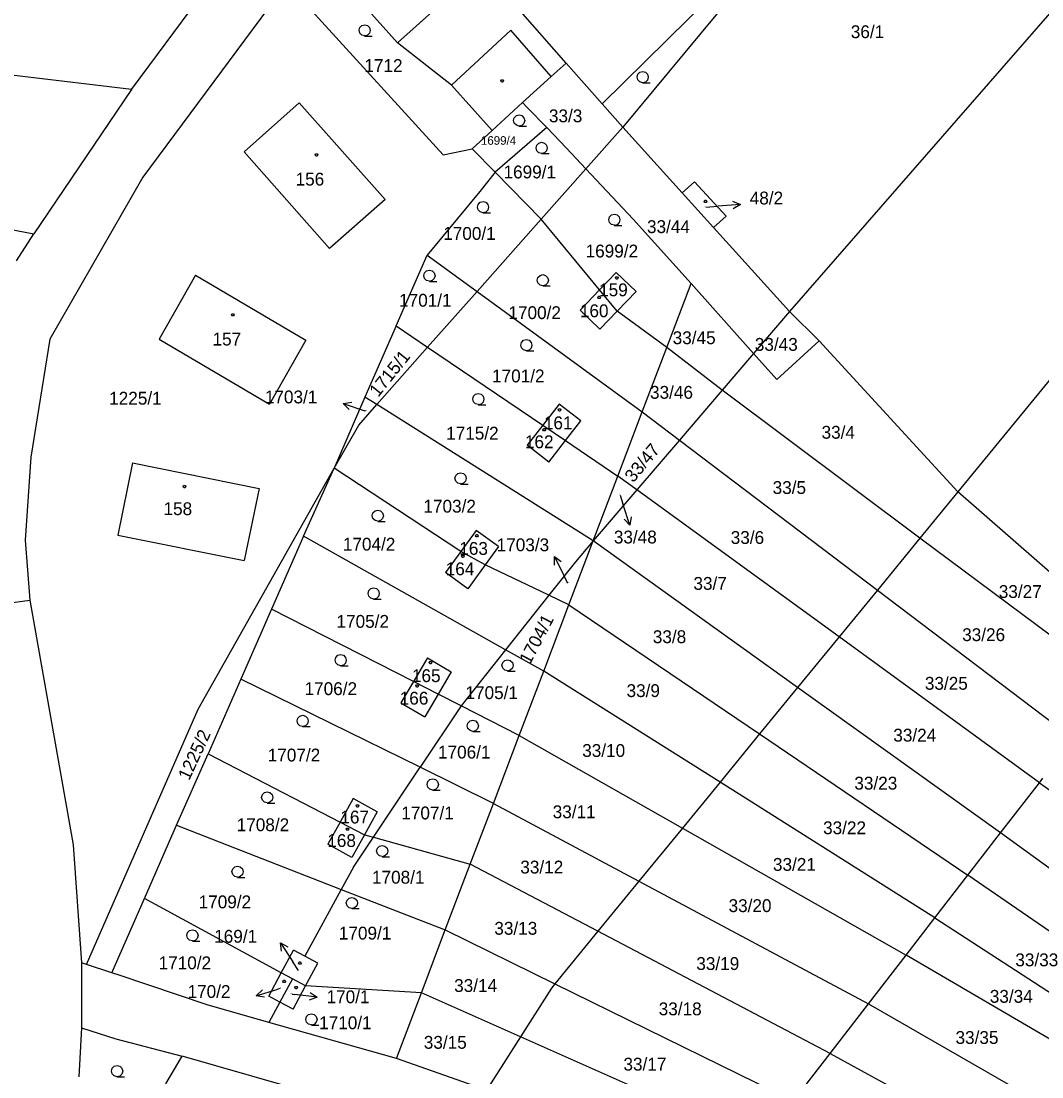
# Model space of a CAD drawing. Extents: x -802857 to -799647, y -1020285 to -1015884.
# Drawn here: x -801708.7 to -801573.5, y -1017921.9 to -1017782.1 of the extents above; entities that cross this region are included whole.
import ezdxf

# ---------------------------------------------------------------- set-up
doc = ezdxf.new("R2010")
doc.units = 0
for name, color, linetype in [('Default', 7, 'Continuous'), ('KN_HRANICE', 7, 'Continuous'), ('KN_KULTURY', 7, 'Continuous'), ('KN_PARCELY', 7, 'Continuous'), ('KN_SLUCKY', 7, 'Continuous')]:
    doc.layers.add(name, color=color, linetype=linetype)

# ---------------------------------------------------------------- blocks, each defined once
blk = doc.blocks.new('304')
at = {"layer": 'Default'}
blk.add_lwpolyline([(0, 0), (-0.38, 0.1), (-0.65, 0.37), (-0.75, 0.74), (-0.65, 1.11), (-0.38, 1.38), (-0.01, 1.48), (0.36, 1.38), (0.63, 1.11), (0.73, 0.73), (0.63, 0.35), (0.36, 0.08), (-0.02, -0.02), (0.98, -0.02)], dxfattribs=at)
blk = doc.blocks.new('10292')
at = {"layer": 'Default'}
blk.add_line((0, 3), (0, 0), dxfattribs=at)
blk.add_lwpolyline([(-0.5, 2), (0, 3), (0.5, 2)], dxfattribs=at)
blk = doc.blocks.new('402')
at = {"layer": 'Default'}
blk.add_lwpolyline([(0.09, 0.15), (0.18, 0), (0.09, -0.15), (-0.09, -0.15), (-0.18, 0), (-0.09, 0.15), (0.09, 0.15)], dxfattribs=at)

msp = doc.modelspace()

# ---------------------------------------------------------------- linework, layer by layer
at = {"layer": 'KN_HRANICE'}
for p, q in [((-801587.49, -1017746.18), (-801629.02, -1017796.14)), ((-801636.53, -1017787.69), (-801656.2, -1017765.17)), ((-801665.9, -1017766.77), (-801692.56, -1017802.78)), ((-801560.55, -1017767.41), (-801606.93, -1017820.56)), ((-801606.88, -1017768.59), (-801631.76, -1017793.06)), ((-801694.1, -1017791.18), (-801681, -1017773.54)), ((-801526.7, -1017773.73), (-801584.65, -1017844.45)), ((-801658.84, -1017785), (-801667.4, -1017775.47)), ((-801670.22, -1017780.7), (-801652.82, -1017799.83)), ((-801651.72, -1017790.61), (-801658.84, -1017785)), ((-801636.53, -1017787.69), (-801638.49, -1017789.43)), ((-801631.76, -1017793.06), (-801636.53, -1017787.69)), ((-801694.1, -1017791.18), (-801711.96, -1017789.03)), ((-801638.49, -1017789.43), (-801642.29, -1017792.91)), ((-801694.1, -1017791.18), (-801707.01, -1017810.3)), ((-801651.72, -1017790.61), (-801646.32, -1017796.61)), ((-801679.14, -1017799.41), (-801671.86, -1017792.92)), ((-801671.86, -1017792.92), (-801660.48, -1017805.72)), ((-801642.29, -1017792.91), (-801646.32, -1017796.61)), ((-801641.68, -1017793.54), (-801642.29, -1017792.91)), ((-801641.68, -1017793.54), (-801639.09, -1017796.22)), ((-801629.02, -1017796.14), (-801631.76, -1017793.06)), ((-801646.32, -1017796.61), (-801648.95, -1017799.02)), ((-801639.09, -1017796.22), (-801645.9, -1017802.13)), ((-801639.09, -1017796.22), (-801636.48, -1017798.92)), ((-801633.91, -1017801.66), (-801629.02, -1017796.14)), ((-801629.02, -1017796.14), (-801621.14, -1017804.85)), ((-801667.86, -1017812.23), (-801679.14, -1017799.41)), ((-801652.82, -1017799.83), (-801648.95, -1017799.02)), ((-801645.9, -1017802.13), (-801648.95, -1017799.02)), ((-801636.48, -1017798.92), (-801633.91, -1017801.66)), ((-801754.22, -1017801.07), (-801707.01, -1017810.3)), ((-801645.9, -1017802.13), (-801647.97, -1017804.68)), ((-801645.9, -1017802.13), (-801639.83, -1017808.34)), ((-801639.83, -1017808.34), (-801633.91, -1017801.66)), ((-801633.91, -1017801.66), (-801627.63, -1017808.36)), ((-801692.56, -1017802.78), (-801704.91, -1017824.25)), ((-801621.14, -1017804.85), (-801619.52, -1017803.38)), ((-801619.52, -1017803.38), (-801615.33, -1017807.93)), ((-801647.97, -1017804.68), (-801654.93, -1017813.11)), ((-801621.14, -1017804.85), (-801616.99, -1017809.44)), ((-801660.48, -1017805.72), (-801667.86, -1017812.23)), ((-801616.99, -1017809.44), (-801615.33, -1017807.93)), ((-801648.32, -1017817.92), (-801639.83, -1017808.34)), ((-801632.1, -1017817.7), (-801639.83, -1017808.34)), ((-801627.63, -1017808.36), (-801619.98, -1017816.88)), ((-801616.99, -1017809.44), (-801606.93, -1017820.56)), ((-801709.32, -1017813.86), (-801707.01, -1017810.3)), ((-801659.05, -1017822.48), (-801654.93, -1017813.11)), ((-801654.93, -1017813.11), (-801648.32, -1017817.92)), ((-801685.6, -1017815.77), (-801690.43, -1017824.24)), ((-801685.6, -1017815.77), (-801670.98, -1017824.37)), ((-801632.1, -1017817.7), (-801629.89, -1017815.39)), ((-801627.26, -1017817.92), (-801629.89, -1017815.39)), ((-801654.87, -1017825.31), (-801648.32, -1017817.92)), ((-801648.32, -1017817.92), (-801626.43, -1017833.85)), ((-801634.67, -1017820.37), (-801632.1, -1017817.7)), ((-801629.76, -1017820.53), (-801632.1, -1017817.7)), ((-801627.26, -1017817.92), (-801629.76, -1017820.53)), ((-801623.2, -1017825.34), (-801619.98, -1017816.88)), ((-801619.98, -1017816.88), (-801611.69, -1017826.12)), ((-801632.04, -1017822.9), (-801634.67, -1017820.37)), ((-801629.76, -1017820.53), (-801632.04, -1017822.9)), ((-801623.2, -1017825.34), (-801629.76, -1017820.53)), ((-801606.93, -1017820.56), (-801611.69, -1017826.12)), ((-801603.03, -1017824.46), (-801606.93, -1017820.56)), ((-801659.05, -1017822.48), (-801663.18, -1017831.89)), ((-801659.05, -1017822.48), (-801654.87, -1017825.31)), ((-801704.91, -1017824.25), (-801707.43, -1017839.85)), ((-801690.43, -1017824.24), (-801675.81, -1017832.84)), ((-801670.98, -1017824.37), (-801675.81, -1017832.84)), ((-801608.61, -1017829.56), (-801603.03, -1017824.46)), ((-801603.03, -1017824.46), (-801584.65, -1017844.45)), ((-801661.59, -1017832.89), (-801654.87, -1017825.31)), ((-801654.87, -1017825.31), (-801639.62, -1017835.62)), ((-801626.43, -1017833.85), (-801623.2, -1017825.34)), ((-801615.84, -1017830.97), (-801623.2, -1017825.34)), ((-801611.69, -1017826.12), (-801615.84, -1017830.97)), ((-801611.69, -1017826.12), (-801608.61, -1017829.56)), ((-801663.18, -1017831.89), (-801667.22, -1017841.33)), ((-801661.59, -1017832.89), (-801663.18, -1017831.89)), ((-801615.84, -1017830.97), (-801621.5, -1017837.59)), ((-801589.67, -1017850.59), (-801615.84, -1017830.97)), ((-801663.99, -1017835.6), (-801661.59, -1017832.89)), ((-801632.93, -1017850.94), (-801661.59, -1017832.89)), ((-801637.45, -1017832.82), (-801639.62, -1017835.62)), ((-801634.57, -1017835.06), (-801637.45, -1017832.82)), ((-801629.66, -1017842.35), (-801626.43, -1017833.85)), ((-801626.43, -1017833.85), (-801621.5, -1017837.59)), ((-801667.22, -1017841.33), (-801663.99, -1017835.6)), ((-801639.62, -1017835.62), (-801641.68, -1017838.27)), ((-801639.62, -1017835.62), (-801636.59, -1017837.67)), ((-801636.59, -1017837.67), (-801634.57, -1017835.06)), ((-801621.5, -1017837.59), (-801627.15, -1017844.18)), ((-801621.5, -1017837.59), (-801595.3, -1017857.46)), ((-801638.8, -1017840.51), (-801641.68, -1017838.27)), ((-801638.8, -1017840.51), (-801636.59, -1017837.67)), ((-801636.59, -1017837.67), (-801629.66, -1017842.35)), ((-801707.43, -1017839.85), (-801708.15, -1017850.85)), ((-801693.95, -1017840.61), (-801695.91, -1017850.17)), ((-801693.95, -1017840.61), (-801677.18, -1017843.99)), ((-801685.23, -1017873.24), (-801667.22, -1017841.33)), ((-801671.28, -1017850.32), (-801667.22, -1017841.33)), ((-801650.45, -1017852.35), (-801667.22, -1017841.33)), ((-801632.93, -1017850.94), (-801629.66, -1017842.35)), ((-801627.15, -1017844.18), (-801629.66, -1017842.35)), ((-801677.18, -1017843.99), (-801679.14, -1017853.55)), ((-801627.15, -1017844.18), (-801632.93, -1017850.94)), ((-801600.38, -1017863.66), (-801627.15, -1017844.18)), ((-801584.65, -1017844.45), (-801589.67, -1017850.59)), ((-801566.54, -1017860.25), (-801584.65, -1017844.45)), ((-801695.91, -1017850.17), (-801679.14, -1017853.55)), ((-801648.43, -1017849.55), (-801650.45, -1017852.35)), ((-801645.48, -1017851.7), (-801648.43, -1017849.55)), ((-801708.15, -1017850.85), (-801707.54, -1017858.79)), ((-801671.28, -1017850.32), (-801675.52, -1017859.98)), ((-801644.53, -1017865.36), (-801671.28, -1017850.32)), ((-801636.14, -1017859.39), (-801632.93, -1017850.94)), ((-801632.93, -1017850.94), (-801635.29, -1017853.7)), ((-801605.86, -1017870.35), (-801632.93, -1017850.94)), ((-801589.67, -1017850.59), (-801595.3, -1017857.46)), ((-801563.11, -1017870.36), (-801589.67, -1017850.59)), ((-801650.45, -1017852.35), (-801652.49, -1017855.13)), ((-801647.25, -1017854.13), (-801650.45, -1017852.35)), ((-801645.48, -1017851.7), (-801647.25, -1017854.13)), ((-801647.25, -1017854.13), (-801649.54, -1017857.28)), ((-801638.8, -1017858.13), (-801647.25, -1017854.13)), ((-801635.29, -1017853.7), (-801638.8, -1017858.13)), ((-801649.54, -1017857.28), (-801652.49, -1017855.13)), ((-801638.8, -1017858.13), (-801644.53, -1017865.36)), ((-801636.14, -1017859.39), (-801638.8, -1017858.13)), ((-801595.3, -1017857.46), (-801600.38, -1017863.66)), ((-801595.3, -1017857.46), (-801569.08, -1017877.35)), ((-801717.29, -1017860.13), (-801707.54, -1017858.79)), ((-801707.54, -1017858.79), (-801701.82, -1017891.2)), ((-801675.52, -1017859.98), (-801679.59, -1017869.24)), ((-801656.73, -1017869.56), (-801675.52, -1017859.98)), ((-801639.49, -1017868.19), (-801636.14, -1017859.39)), ((-801636.14, -1017859.39), (-801610.9, -1017876.51)), ((-801600.38, -1017863.66), (-801605.86, -1017870.35)), ((-801573.84, -1017882.97), (-801600.38, -1017863.66)), ((-801644.53, -1017865.36), (-801650.41, -1017872.78)), ((-801639.49, -1017868.19), (-801644.53, -1017865.36)), ((-801654.89, -1017866.43), (-801656.73, -1017869.56)), ((-801654.89, -1017866.43), (-801651.74, -1017868.29)), ((-801651.74, -1017868.29), (-801653.47, -1017871.22)), ((-801642.73, -1017876.71), (-801639.49, -1017868.19)), ((-801616.14, -1017882.9), (-801639.49, -1017868.19)), ((-801679.59, -1017869.24), (-801683.94, -1017879.14)), ((-801655.86, -1017880.92), (-801679.59, -1017869.24)), ((-801656.73, -1017869.56), (-801658.39, -1017872.37)), ((-801653.47, -1017871.22), (-801656.73, -1017869.56)), ((-801605.86, -1017870.35), (-801610.9, -1017876.51)), ((-801578.98, -1017889.62), (-801605.86, -1017870.35)), ((-801658.39, -1017872.37), (-801655.25, -1017874.23)), ((-801653.47, -1017871.22), (-801655.25, -1017874.23)), ((-801650.41, -1017872.78), (-801653.47, -1017871.22)), ((-801700.05, -1017907.03), (-801685.23, -1017873.24)), ((-801650.41, -1017872.78), (-801655.86, -1017880.92)), ((-801642.73, -1017876.71), (-801650.41, -1017872.78)), ((-801646.15, -1017885.7), (-801642.73, -1017876.71)), ((-801642.73, -1017876.71), (-801621.12, -1017888.98)), ((-801610.9, -1017876.51), (-801616.14, -1017882.9)), ((-801610.9, -1017876.51), (-801583.31, -1017895.22)), ((-801688.1, -1017888.6), (-801683.94, -1017879.14)), ((-801683.94, -1017879.14), (-801666.46, -1017888.17)), ((-801662.05, -1017890.18), (-801655.86, -1017880.92)), ((-801646.15, -1017885.7), (-801655.86, -1017880.92)), ((-801573.84, -1017882.97), (-801573.38, -1017882.38)), ((-801616.14, -1017882.9), (-801621.12, -1017888.98)), ((-801587.67, -1017900.85), (-801616.14, -1017882.9)), ((-801578.98, -1017889.62), (-801573.84, -1017882.97)), ((-801573.84, -1017882.97), (-801548.75, -1017900.91)), ((-801664.73, -1017885.06), (-801666.46, -1017888.17)), ((-801661.54, -1017886.83), (-801664.73, -1017885.06)), ((-801649.21, -1017893.75), (-801646.15, -1017885.7)), ((-801646.15, -1017885.7), (-801626.87, -1017896)), ((-801661.54, -1017886.83), (-801663.22, -1017889.85)), ((-801692.35, -1017898.29), (-801688.1, -1017888.6)), ((-801688.1, -1017888.6), (-801666.31, -1017897.09)), ((-801666.46, -1017888.17), (-801668.08, -1017891.09)), ((-801666.46, -1017888.17), (-801663.22, -1017889.85)), ((-801621.12, -1017888.98), (-801626.87, -1017896)), ((-801621.12, -1017888.98), (-801591.49, -1017905.8)), ((-801663.22, -1017889.85), (-801664.89, -1017892.87)), ((-801664.7, -1017894.14), (-801662.05, -1017890.18)), ((-801663.22, -1017889.85), (-801662.05, -1017890.18)), ((-801662.05, -1017890.18), (-801649.21, -1017893.75)), ((-801583.31, -1017895.22), (-801578.98, -1017889.62)), ((-801554.19, -1017907.62), (-801578.98, -1017889.62)), ((-801701.82, -1017891.2), (-801700.72, -1017906.81)), ((-801664.89, -1017892.87), (-801668.08, -1017891.09)), ((-801664.7, -1017894.14), (-801666.31, -1017897.09)), ((-801652.52, -1017902.46), (-801649.21, -1017893.75)), ((-801632.31, -1017902.64), (-801649.21, -1017893.75)), ((-801626.87, -1017896), (-801632.31, -1017902.64)), ((-801626.87, -1017896), (-801596.46, -1017912.23)), ((-801587.67, -1017900.85), (-801583.31, -1017895.22)), ((-801558.14, -1017912.49), (-801583.31, -1017895.22)), ((-801666.31, -1017897.09), (-801671.13, -1017905.94)), ((-801666.31, -1017897.09), (-801652.52, -1017902.46)), ((-801696.68, -1017908.14), (-801692.35, -1017898.29)), ((-801674.24, -1017908.14), (-801692.35, -1017898.29)), ((-801591.49, -1017905.8), (-801587.67, -1017900.85)), ((-801587.67, -1017900.85), (-801562.14, -1017917.44)), ((-801655.69, -1017910.79), (-801652.52, -1017902.46)), ((-801652.52, -1017902.46), (-801638, -1017909.59)), ((-801632.31, -1017902.64), (-801638, -1017909.59)), ((-801601.56, -1017918.81), (-801632.31, -1017902.64)), ((-801674.24, -1017908.14), (-801672.63, -1017905.14)), ((-801671.13, -1017905.94), (-801672.63, -1017905.14)), ((-801669.41, -1017906.86), (-801671.13, -1017905.94)), ((-801596.46, -1017912.23), (-801591.49, -1017905.8)), ((-801565.18, -1017921.19), (-801591.49, -1017905.8)), ((-801700.72, -1017906.81), (-801700.71, -1017915.44)), ((-801700.05, -1017907.03), (-801700.72, -1017906.81)), ((-801696.68, -1017908.14), (-801700.05, -1017907.03)), ((-801671.02, -1017909.86), (-801669.41, -1017906.86)), ((-801695.73, -1017908.45), (-801696.68, -1017908.14)), ((-801684.06, -1017912.38), (-801695.73, -1017908.45)), ((-801675.89, -1017911.22), (-801674.24, -1017908.14)), ((-801672.76, -1017908.93), (-801674.43, -1017912)), ((-801672.76, -1017908.93), (-801674.24, -1017908.14)), ((-801671.02, -1017909.86), (-801672.76, -1017908.93)), ((-801672.67, -1017912.94), (-801671.02, -1017909.86)), ((-801655.69, -1017910.79), (-801671.02, -1017909.86)), ((-801638.47, -1017910.16), (-801642.56, -1017916.61)), ((-801638, -1017909.59), (-801638.47, -1017910.16)), ((-801638, -1017909.59), (-801606.41, -1017925.09)), ((-801674.43, -1017912), (-801675.89, -1017911.22)), ((-801659, -1017919.5), (-801655.69, -1017910.79)), ((-801642.56, -1017916.61), (-801655.69, -1017910.79)), ((-801675.91, -1017914.7), (-801684.06, -1017912.38)), ((-801674.43, -1017912), (-801675.91, -1017914.7)), ((-801672.67, -1017912.94), (-801674.43, -1017912)), ((-801601.56, -1017918.81), (-801596.46, -1017912.23)), ((-801596.46, -1017912.23), (-801570.17, -1017927.35)), ((-801700.71, -1017915.44), (-801701.04, -1017921.92)), ((-801700.71, -1017915.44), (-801696.14, -1017916.89)), ((-801659, -1017919.5), (-801675.91, -1017914.7)), ((-801696.14, -1017916.89), (-801687.37, -1017919.18)), ((-801642.56, -1017916.61), (-801647.06, -1017923.69)), ((-801610.75, -1017930.7), (-801642.56, -1017916.61)), ((-801689.53, -1017922.82), (-801687.37, -1017919.18)), ((-801669.21, -1017924.37), (-801687.37, -1017919.18)), ((-801647.06, -1017923.69), (-801659, -1017919.5)), ((-801606.41, -1017925.09), (-801601.56, -1017918.81)), ((-801601.56, -1017918.81), (-801575.03, -1017933.33))]:
    msp.add_line(p, q, dxfattribs=at)
at = {"layer": 'KN_PARCELY'}
for p, q in [((-801618.02, -1017806.73), (-801616.43, -1017806.61)), ((-801663.11, -1017833.73), (-801663.19, -1017833.7)), ((-801629.38, -1017844.9), (-801629.01, -1017846.02)), ((-801636.29, -1017856.55), (-801636.72, -1017855.7)), ((-801671.96, -1017907.81), (-801672.71, -1017906.66)), ((-801674.38, -1017910.21), (-801674.68, -1017910.3)), ((-801672.82, -1017910.97), (-801672.47, -1017911.01))]:
    msp.add_line(p, q, dxfattribs=at)
at = {"layer": 'KN_SLUCKY'}
for p, q in [((-801652.2, -1017779.01), (-801658.84, -1017785)), ((-801651.72, -1017790.61), (-801643.83, -1017783.33)), ((-801638.49, -1017789.43), (-801643.83, -1017783.33))]:
    msp.add_line(p, q, dxfattribs=at)

# ---------------------------------------------------------------- block references
at = {"layer": 'KN_KULTURY'}
for name, p in [('304', (-801663.19, -1017784.07)), ('402', (-801645, -1017790.03)), ('304', (-801626.37, -1017790.27)), ('304', (-801642.73, -1017796.01)), ('304', (-801639.75, -1017799.64)), ('402', (-801669.57, -1017799.83)), ('304', (-801647.51, -1017807.49)), ('402', (-801618.08, -1017805.98)), ('304', (-801630.12, -1017809.15)), ('304', (-801654.61, -1017816.56)), ('304', (-801639.6, -1017817.16)), ('402', (-801629.79, -1017816.13)), ('402', (-801632.15, -1017818.7)), ('402', (-801680.68, -1017821.01)), ('304', (-801641.77, -1017825.76)), ('304', (-801648.14, -1017832.9)), ('402', (-801637.41, -1017833.6)), ('402', (-801639.42, -1017836.22)), ('304', (-801650.49, -1017843.39)), ('402', (-801687.08, -1017843.76)), ('304', (-801661.45, -1017848.34)), ('402', (-801648.35, -1017850.26)), ('402', (-801650.21, -1017852.98)), ('304', (-801662, -1017858.64)), ('304', (-801666.37, -1017867.47)), ('402', (-801654.48, -1017867.06)), ('304', (-801644.27, -1017868.15)), ('402', (-801656.25, -1017870.15)), ('304', (-801671.4, -1017875.52)), ('304', (-801648.87, -1017876.17)), ('304', (-801654.17, -1017883.93)), ('304', (-801676.1, -1017885.64)), ('402', (-801664.16, -1017886.03)), ('402', (-801665.49, -1017889.11)), ('304', (-801660.87, -1017892.74)), ('304', (-801680.03, -1017895.48)), ('304', (-801664.89, -1017899.62)), ('304', (-801686, -1017903.92)), ('402', (-801671.78, -1017906.84)), ('402', (-801673.88, -1017909.28)), ('402', (-801672.27, -1017910.09)), ('304', (-801670.24, -1017915.04)), ('304', (-801695.98, -1017921.89))]:
    msp.add_blockref(name, p, dxfattribs=at)
at = {"layer": 'KN_PARCELY'}
for p, rotation in [((-801616.43, -1017806.61), -85.78239900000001), ((-801663.19, -1017833.7), 71.104062), ((-801629.01, -1017846.02), -161.58471600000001), ((-801636.72, -1017855.7), 26.642537), ((-801672.71, -1017906.66), 33.231552), ((-801674.68, -1017910.3), 106.856629), ((-801672.47, -1017911.01), -96.840485)]:
    msp.add_blockref('10292', p, dxfattribs=dict(at, rotation=rotation))

# ---------------------------------------------------------------- texts
for s, height, p in [('36/1', 1.7, (-801598.82, -1017784.37)), ('1712', 1.7, (-801663.24, -1017788.85)), ('33/3', 1.7, (-801638.8, -1017795.51)), ('1699/4', 1.14, (-801647.8, -1017798.49)), ('1699/1', 1.7, (-801644.81, -1017802.94)), ('156', 1.7, (-801672.35, -1017803.89)), ('48/2', 1.7, (-801612.2, -1017806.39)), ('48/2', 0.1, (-801618.22, -1017806.73)), ('1700/1', 1.7, (-801652.8, -1017811.08)), ('33/44', 1.7, (-801625.81, -1017810.18)), ('1699/2', 1.7, (-801633.94, -1017813.41)), ('159', 1.7, (-801632.15, -1017818.55)), ('1701/1', 1.7, (-801658.64, -1017819.93)), ('1700/2', 1.7, (-801644.16, -1017821.57)), ('160', 1.7, (-801634.7, -1017821.32)), ('157', 1.7, (-801683.35, -1017825.07)), ('33/45', 1.7, (-801622.41, -1017824.89)), ('33/43', 1.7, (-801611.53, -1017825.77)), ('1701/2', 1.7, (-801646.33, -1017829.95)), ('33/46', 1.7, (-801625.41, -1017832.12)), ('1225/1', 1.7, (-801697.04, -1017832.9)), ('1703/1', 1.7, (-801676.42, -1017832.73)), ('1703/1', 0.1, (-801663.39, -1017833.73)), ('161', 1.7, (-801639.47, -1017836.16)), ('1715/2', 1.7, (-801652.41, -1017837.53)), ('33/4', 1.7, (-801602.69, -1017837.41)), ('162', 1.7, (-801641.98, -1017838.67)), ('33/5', 1.7, (-801609.17, -1017844.73)), ('158', 1.7, (-801689.84, -1017847.53)), ('1703/2', 1.7, (-801655.42, -1017847.2)), ('33/48', 0.1, (-801629.62, -1017844.9)), ('33/48', 1.7, (-801630.2, -1017851.28)), ('33/6', 1.7, (-801614.72, -1017851.34)), ('1704/2', 1.7, (-801666.09, -1017852.23)), ('163', 1.7, (-801650.67, -1017852.79)), ('1703/3', 1.7, (-801645.72, -1017852.31)), ('164', 1.7, (-801652.47, -1017855.49)), ('33/7', 1.7, (-801619.66, -1017857.42)), ('1703/3', 0.1, (-801636.59, -1017856.55)), ('33/27', 1.7, (-801579.22, -1017858.5)), ('1705/2', 1.7, (-801666.93, -1017862.45)), ('33/8', 1.7, (-801625.04, -1017864.48)), ('33/26', 1.7, (-801584.07, -1017864.21)), ('165', 1.7, (-801656.94, -1017869.64)), ('1706/2', 1.7, (-801671.16, -1017871.36)), ('33/25', 1.7, (-801589.01, -1017870.65)), ('166', 1.7, (-801658.56, -1017872.62)), ('1705/1', 1.7, (-801649.85, -1017871.89)), ('33/9', 1.7, (-801628.52, -1017871.62)), ('33/24', 1.7, (-801593.19, -1017877.52)), ('1706/1', 1.7, (-801653.49, -1017879.76)), ('33/10', 1.7, (-801634.39, -1017879.55)), ('1707/2', 1.7, (-801676.04, -1017880.15)), ('33/23', 1.7, (-801598.35, -1017883.87)), ('1707/1', 1.7, (-801658.35, -1017887.82)), ('33/11', 1.7, (-801638.3, -1017887.66)), ('1708/2', 1.7, (-801680.15, -1017889.38)), ('167', 1.7, (-801666.42, -1017888.36)), ('33/22', 1.7, (-801602.49, -1017889.78)), ('168', 1.7, (-801668.15, -1017891.47)), ('33/12', 1.7, (-801642.59, -1017894.98)), ('33/21', 1.7, (-801609.13, -1017894.63)), ('1708/1', 1.7, (-801662.23, -1017896.33)), ('1709/2', 1.7, (-801685.19, -1017899.59)), ('33/20', 1.7, (-801615.01, -1017900.09)), ('1709/1', 1.7, (-801666.62, -1017903.73)), ('33/13', 1.7, (-801646.03, -1017903.09)), ('169/1', 1.7, (-801683.13, -1017904.15)), ('1710/2', 1.7, (-801690.49, -1017907.66)), ('33/19', 1.7, (-801619.28, -1017907.76)), ('33/33', 1.7, (-801577.03, -1017907.27)), ('169/1', 0.1, (-801672.2, -1017907.81)), ('33/14', 1.7, (-801651.35, -1017910.67)), ('170/2', 1.7, (-801686.66, -1017911.46)), ('170/2', 0.1, (-801674.63, -1017910.21)), ('33/34', 1.7, (-801580.41, -1017912.1)), ('170/1', 0.1, (-801673.06, -1017910.97)), ('170/1', 1.7, (-801668.25, -1017912.16)), ('33/18', 1.7, (-801624.26, -1017913.76)), ('1710/1', 1.7, (-801669.23, -1017915.6)), ('33/35', 1.7, (-801584.95, -1017917.55)), ('33/15', 1.7, (-801655.37, -1017918.19)), ('33/17', 1.7, (-801628.93, -1017921.08))]:
    msp.add_text(s, height=height, dxfattribs=at).set_placement(p)
for s, rotation, p in [('1715/1', 51.28, (-801661.41, -1017832)), ('33/47', 50.306, (-801627.62, -1017843.32)), ('1704/1', 62.281, (-801641.32, -1017867.42)), ('1225/2', 65.145, (-801686.45, -1017882.76))]:
    msp.add_text(s, height=1.7, rotation=rotation, dxfattribs=at).set_placement(p)

doc.saveas('drawing.dxf')
